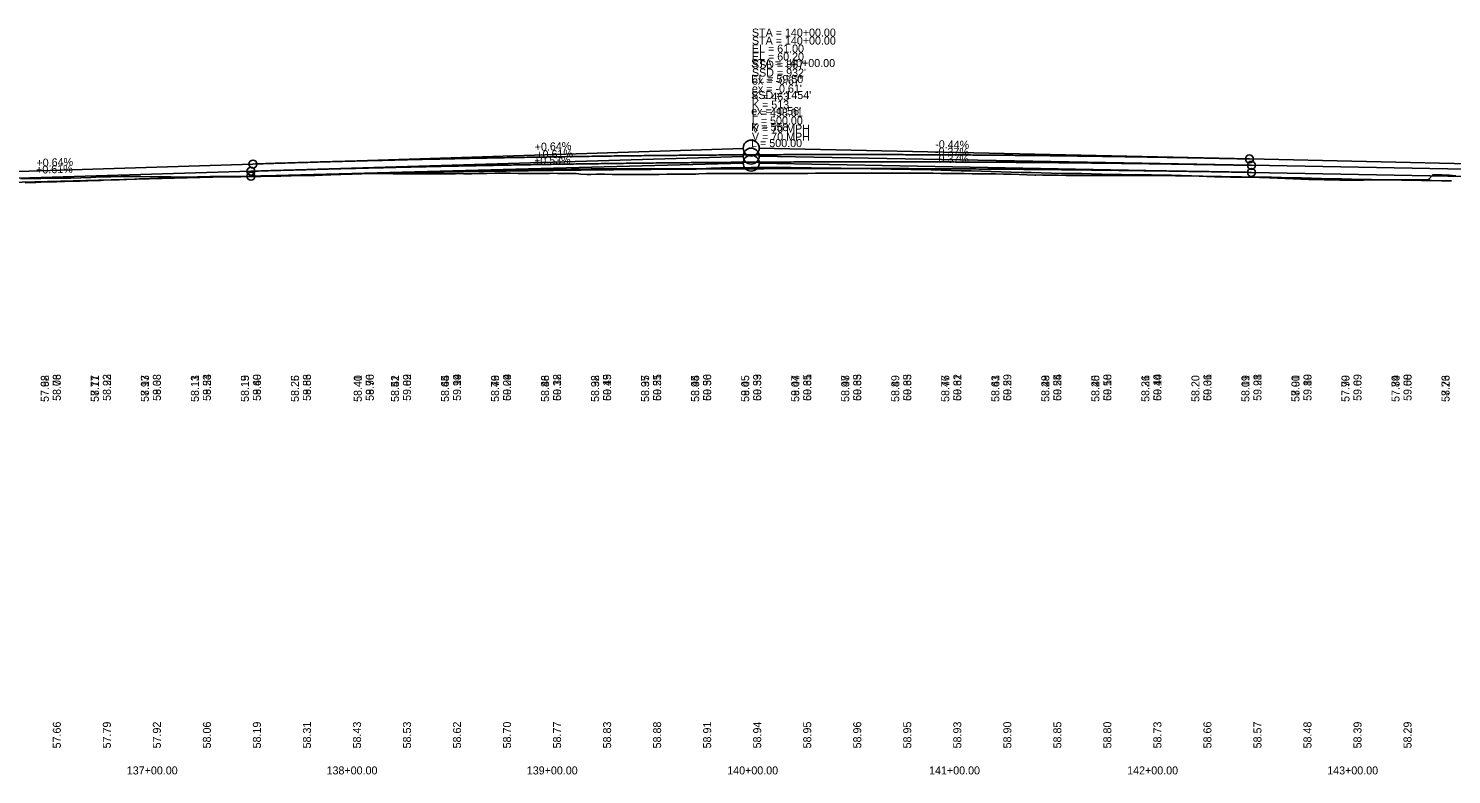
# Model space of a CAD drawing. Extents: x 3880794 to 3915434, y 287517 to 300173.
# Drawn here: x 3894177 to 3894888, y 296520 to 296893 of the extents above; entities that cross this region are included whole.
import ezdxf

# ---------------------------------------------------------------- set-up
doc = ezdxf.new("R2010")
doc.units = 0
for name, color, linetype in [('Level 1', 7, 'Continuous'), ('Level 2', 7, 'Continuous'), ('Level 30', 7, 'Continuous'), ('Level 31', 7, 'Continuous'), ('Level 32', 7, 'Continuous')]:
    doc.layers.add(name, color=color, linetype=linetype)

msp = doc.modelspace()

# ---------------------------------------------------------------- linework, layer by layer
at = {"layer": 'Level 1'}
for p, q in [((3894288.3, 296821.19), (3894534.3, 296828.64)), ((3894788.3, 296824.15), (3894542.3, 296828.68)), ((3893888.3, 296809.08), (3894288.3, 296821.19)), ((3894288.3, 296818.69), (3894534.3, 296825.15)), ((3894788.3, 296820.61), (3894542.3, 296825.18)), ((3894788.3, 296824.15), (3895938.3, 296802.96)), ((3894788.3, 296820.61), (3895938.3, 296799.26)), ((3893788.3, 296805.57), (3894288.3, 296818.69))]:
    msp.add_line(p, q, dxfattribs=at)
for points in [[(3894285.02, 296818.65), (3894288.94, 296818.69), (3894292.85, 296818.73), (3894294.38, 296818.75), (3894296.76, 296818.79), (3894298.01, 296818.81), (3894300.67, 296818.82), (3894301.29, 296818.82), (3894304.58, 296818.88), (3894308.49, 296818.94), (3894312.4, 296819.01), (3894316.31, 296819.08), (3894316.9, 296819.09), (3894320.22, 296819.15), (3894321.05, 296819.17), (3894324.13, 296819.27), (3894328.04, 296819.41), (3894331.95, 296819.55), (3894335.87, 296819.68), (3894338.96, 296819.79), (3894339.78, 296819.82), (3894342.78, 296819.92), (3894343.69, 296819.95), (3894345.76, 296820.03), (3894347.6, 296820.05), (3894349.61, 296820.08), (3894351.51, 296820.05), (3894355.42, 296819.99), (3894359.33, 296819.93), (3894363.24, 296819.88), (3894366.73, 296819.83), (3894367.15, 296819.83), (3894371.12, 296819.85), (3894374.97, 296819.83), (3894375.35, 296819.83), (3894378.88, 296819.86), (3894382.79, 296819.89), (3894386.71, 296819.93), (3894390.62, 296819.97), (3894392.25, 296819.99), (3894394.53, 296819.95), (3894398.69, 296819.9), (3894402.35, 296820), (3894406.26, 296820.1), (3894410.17, 296820.21), (3894410.58, 296820.22), (3894414.08, 296820.19), (3894417.04, 296820.17), (3894417.99, 296820.17), (3894421.9, 296820.13), (3894425.81, 296820.1), (3894427.17, 296820.09), (3894429.73, 296820.1), (3894433.32, 296820.1), (3894433.64, 296820.1), (3894436.37, 296820.1), (3894437.55, 296820.15), (3894438.2, 296820.17), (3894441.46, 296820.12), (3894445.37, 296820.05), (3894447.1, 296820.02), (3894449.28, 296820), (3894450.86, 296819.99), (3894453.19, 296819.81), (3894456.13, 296819.57), (3894457.1, 296819.58), (3894458.11, 296819.58), (3894461.01, 296819.66), (3894461.43, 296819.67), (3894462.6, 296819.66), (3894464.92, 296819.66), (3894468.83, 296819.65), (3894472.74, 296819.64), (3894476.65, 296819.64), (3894480.56, 296819.63), (3894483.18, 296819.63), (3894484.48, 296819.62), (3894486.06, 296819.61), (3894488.39, 296819.61), (3894489.07, 296819.61), (3894492.3, 296819.64), (3894496.21, 296819.67), (3894500.12, 296819.71), (3894504.03, 296819.75), (3894507.94, 296819.78), (3894510.72, 296819.81), (3894512.14, 296819.98), (3894515.76, 296820.02), (3894519.7, 296819.99), (3894523.58, 296820), (3894527.5, 296820.01), (3894531.41, 296820.01), (3894535.32, 296820.02), (3894539.23, 296820.03), (3894540.78, 296820.03), (3894541.43, 296820.03), (3894543.14, 296820.04), (3894545.19, 296820.05), (3894547.05, 296820.05), (3894550.96, 296820.06), (3894554.87, 296820.07)], [(3894554.87, 296820.07), (3894558.78, 296820.08), (3894562.69, 296820.08), (3894565.76, 296820.09), (3894566.6, 296820.1), (3894570.51, 296820.18), (3894571.13, 296820.19), (3894574.43, 296820.2), (3894575.01, 296820.2), (3894578.34, 296820.19), (3894582.25, 296820.19), (3894586.16, 296820.18), (3894590.07, 296820.17), (3894593.98, 296820.16), (3894595.12, 296820.16), (3894598.13, 296820.18), (3894600.03, 296820.18), (3894601.8, 296820.17), (3894602.96, 296820.16), (3894605.71, 296820.17), (3894609.62, 296820.2), (3894613.53, 296820.22), (3894617.44, 296820.23), (3894621.35, 296820.25), (3894623.7, 296820.26), (3894625.27, 296820.23), (3894626.43, 296820.21), (3894627.72, 296820.21), (3894629.18, 296820.19), (3894633.09, 296820.14), (3894637, 296820.09), (3894640.91, 296820.04), (3894644.82, 296819.99), (3894648.73, 296819.94), (3894651.02, 296819.91), (3894652.64, 296819.89), (3894654.9, 296819.86), (3894656.55, 296819.87), (3894657.31, 296819.87), (3894659.8, 296819.91), (3894660.46, 296819.89), (3894664.37, 296819.77), (3894668.29, 296819.66), (3894672.2, 296819.54), (3894676.11, 296819.42), (3894680.02, 296819.3), (3894680.52, 296819.29), (3894682.73, 296819.33), (3894683.93, 296819.29), (3894687.84, 296819.18), (3894689.88, 296819.18), (3894691.75, 296819.17), (3894695.66, 296819.15), (3894699.57, 296819.12), (3894703.48, 296819.09), (3894707.39, 296819.06), (3894710.44, 296819.03), (3894711.3, 296819.02), (3894712.68, 296819.01), (3894713.71, 296819), (3894715.21, 296819), (3894716.12, 296819.01), (3894719.12, 296819.02), (3894723.04, 296819.04), (3894726.95, 296819.06), (3894730.86, 296819.07), (3894734.77, 296819.09), (3894736.19, 296819.09), (3894738.68, 296819.08), (3894739.08, 296819.08), (3894742.59, 296819.08), (3894745.5, 296819.05), (3894746.5, 296819.03), (3894750.41, 296818.97), (3894754.32, 296818.91), (3894758.23, 296818.85), (3894762.14, 296818.78), (3894764, 296818.75), (3894766.06, 296818.62), (3894767.16, 296818.54), (3894769.97, 296818.42), (3894770.47, 296818.39), (3894773.88, 296818.36), (3894777.79, 296818.31), (3894781.7, 296818.27), (3894785.61, 296818.23), (3894788.74, 296818.19), (3894789.52, 296818.16), (3894792.29, 296818.08), (3894793.43, 296818.06), (3894794.57, 296818.05), (3894797.34, 296817.91), (3894801.25, 296817.72), (3894801.84, 296817.69), (3894805.16, 296817.57), (3894809.07, 296817.42), (3894812.98, 296817.26), (3894816.9, 296817.11), (3894817.6, 296817.08), (3894820.81, 296817.03), (3894824.72, 296816.96)], [(3894824.72, 296816.96), (3894826.53, 296816.93), (3894828.71, 296816.85), (3894832.54, 296816.8), (3894836.45, 296816.74), (3894840.36, 296816.69), (3894840.71, 296816.68), (3894844.27, 296816.76), (3894848.18, 296816.86), (3894852.09, 296816.94), (3894856, 296816.93), (3894857.84, 296816.93), (3894859.92, 296816.94), (3894863.83, 296816.95), (3894867.74, 296816.97), (3894871.65, 296816.98), (3894874.37, 296816.98), (3894875.56, 296816.97), (3894876.78, 296816.95), (3894877.16, 296817.38), (3894878.93, 296819.42), (3894879.69, 296819.41), (3894883.38, 296819.32), (3894886.53, 296819.24), (3894887.29, 296819.17), (3894890.4, 296818.87)], [(3894175.52, 296815.48), (3894179.43, 296815.61), (3894180.79, 296815.65), (3894183.34, 296815.72), (3894187.25, 296815.83), (3894191.17, 296815.95), (3894193.91, 296816.03), (3894195.08, 296816.06), (3894198.99, 296816.16), (3894202.93, 296816.27), (3894206.81, 296816.39), (3894210.72, 296816.52), (3894213.35, 296816.6), (3894214.63, 296816.66), (3894218.54, 296816.82), (3894221.46, 296816.92), (3894221.85, 296816.94), (3894222.45, 296816.96), (3894224.98, 296817.08), (3894226.36, 296817.13), (3894230.27, 296817.28), (3894232.48, 296817.37), (3894234.18, 296817.44), (3894238.09, 296817.61), (3894242, 296817.78), (3894245.59, 296817.94), (3894245.92, 296817.95), (3894249.83, 296818.09), (3894252.07, 296818.17), (3894253.74, 296818.2), (3894257.65, 296818.28), (3894261.56, 296818.37), (3894265.47, 296818.45), (3894267.87, 296818.5), (3894269.38, 296818.51), (3894272.84, 296818.53), (3894273.29, 296818.54), (3894277.29, 296818.58), (3894281.11, 296818.61), (3894285.02, 296818.65)]]:
    msp.add_lwpolyline(points, dxfattribs=at)
for centre in [(3894538.3, 296828.76), (3894538.3, 296825.26)]:
    msp.add_circle(centre, 4, dxfattribs=at)
for points in [[(3894288.3, 296821.19), (3894298.3, 296821.49), (3894308.3, 296821.77), (3894318.3, 296822.05), (3894328.3, 296822.32), (3894338.3, 296822.58), (3894348.3, 296822.83), (3894358.3, 296823.07), (3894368.3, 296823.3), (3894378.3, 296823.52), (3894388.3, 296823.73), (3894398.3, 296823.93), (3894408.3, 296824.12), (3894418.3, 296824.3), (3894428.3, 296824.47), (3894438.3, 296824.63), (3894448.3, 296824.79), (3894458.3, 296824.93), (3894468.3, 296825.06), (3894478.3, 296825.18), (3894488.3, 296825.29), (3894498.3, 296825.4), (3894508.3, 296825.49), (3894518.3, 296825.57), (3894528.3, 296825.65), (3894538.3, 296825.71), (3894548.3, 296825.77), (3894558.3, 296825.81), (3894568.3, 296825.85), (3894578.3, 296825.87), (3894588.3, 296825.89), (3894598.3, 296825.89), (3894608.3, 296825.89), (3894618.3, 296825.88), (3894628.3, 296825.85), (3894638.3, 296825.82), (3894648.3, 296825.78), (3894658.3, 296825.72), (3894668.3, 296825.66), (3894678.3, 296825.59), (3894688.3, 296825.51), (3894698.3, 296825.41), (3894708.3, 296825.31), (3894718.3, 296825.2), (3894728.3, 296825.08), (3894738.3, 296824.95), (3894748.3, 296824.81), (3894758.3, 296824.66), (3894768.3, 296824.5), (3894778.3, 296824.33), (3894788.3, 296824.15)], [(3894288.3, 296818.69), (3894298.3, 296818.95), (3894308.3, 296819.2), (3894318.3, 296819.44), (3894328.3, 296819.67), (3894338.3, 296819.89), (3894348.3, 296820.11), (3894358.3, 296820.31), (3894368.3, 296820.51), (3894378.3, 296820.69), (3894388.3, 296820.87), (3894398.3, 296821.04), (3894408.3, 296821.2), (3894418.3, 296821.35), (3894428.3, 296821.49), (3894438.3, 296821.62), (3894448.3, 296821.75), (3894458.3, 296821.86), (3894468.3, 296821.97), (3894478.3, 296822.06), (3894488.3, 296822.15), (3894498.3, 296822.23), (3894508.3, 296822.3), (3894518.3, 296822.36), (3894528.3, 296822.41), (3894538.3, 296822.46), (3894548.3, 296822.49), (3894558.3, 296822.51), (3894568.3, 296822.53), (3894578.3, 296822.54), (3894588.3, 296822.54), (3894598.3, 296822.52), (3894608.3, 296822.5), (3894618.3, 296822.48), (3894628.3, 296822.44), (3894638.3, 296822.39), (3894648.3, 296822.34), (3894658.3, 296822.27), (3894668.3, 296822.2), (3894678.3, 296822.11), (3894688.3, 296822.02), (3894698.3, 296821.92), (3894708.3, 296821.81), (3894718.3, 296821.69), (3894728.3, 296821.57), (3894738.3, 296821.43), (3894748.3, 296821.29), (3894758.3, 296821.13), (3894768.3, 296820.97), (3894778.3, 296820.8), (3894788.3, 296820.61)]]:
    msp.add_spline(points, degree=3, dxfattribs=at)
at = {"layer": 'Level 2'}
for p, q in [((3894289.29, 296824.8), (3894534.3, 296832.63)), ((3894787.3, 296827.33), (3894542.3, 296832.67)), ((3894787.3, 296827.33), (3895938.3, 296802.26)), ((3893888.3, 296811.99), (3894289.29, 296824.8))]:
    msp.add_line(p, q, dxfattribs=at)
for points in [[(3894173.3, 296817.4), (3894178.3, 296817.55), (3894183.3, 296817.62), (3894188.3, 296817.67), (3894193.3, 296817.71), (3894198.3, 296817.81), (3894203.3, 296817.93), (3894208.3, 296818.09), (3894213.3, 296818.32), (3894218.3, 296818.42), (3894223.3, 296818.5), (3894228.3, 296818.57), (3894233.3, 296818.62), (3894238.3, 296818.39), (3894243.3, 296818.49), (3894248.3, 296818.38), (3894253.3, 296818.29), (3894258.3, 296818.28), (3894263.3, 296818.32), (3894268.3, 296818.33), (3894273.3, 296818.34), (3894278.3, 296818.35), (3894283.3, 296818.4), (3894288.3, 296818.52), (3894293.3, 296818.62), (3894298.3, 296818.71), (3894303.3, 296818.8), (3894308.3, 296818.94), (3894313.3, 296819.05), (3894318.3, 296819.19), (3894323.3, 296819.33), (3894328.3, 296819.46), (3894333.3, 296819.59), (3894338.3, 296819.78), (3894343.3, 296819.89), (3894348.3, 296819.99), (3894353.3, 296820.09), (3894358.3, 296820.19), (3894363.3, 296820.33), (3894368.3, 296820.47), (3894373.3, 296820.6), (3894378.3, 296820.73), (3894383.3, 296820.86), (3894388.3, 296820.99), (3894393.3, 296821.05), (3894398.3, 296821.17), (3894403.3, 296821.31), (3894408.3, 296821.44), (3894413.3, 296821.57), (3894418.3, 296821.72), (3894423.3, 296821.83), (3894428.3, 296821.86), (3894433.3, 296821.95), (3894438.3, 296822.04), (3894443.3, 296822.13), (3894448.3, 296822.22), (3894453.3, 296822.27), (3894458.3, 296822.32), (3894463.3, 296822.36), (3894468.3, 296822.4), (3894473.3, 296822.43), (3894478.3, 296822.46), (3894483.3, 296822.48), (3894488.3, 296822.49), (3894493.3, 296822.47), (3894498.3, 296822.44), (3894503.3, 296822.41), (3894508.3, 296822.38), (3894513.3, 296822.48), (3894518.3, 296822.65), (3894523.3, 296822.82), (3894528.3, 296822.99), (3894533.3, 296822.97), (3894538.3, 296823)], [(3894538.3, 296823), (3894543.3, 296823.03), (3894548.3, 296823.06), (3894553.3, 296823.12), (3894558.3, 296823.03), (3894563.3, 296822.93), (3894568.3, 296822.83), (3894573.3, 296822.75), (3894578.3, 296822.7), (3894583.3, 296822.65), (3894588.3, 296822.6), (3894593.3, 296822.54), (3894598.3, 296822.48), (3894603.3, 296822.38), (3894608.3, 296822.29), (3894613.3, 296822.19), (3894618.3, 296822.1), (3894623.3, 296822), (3894628.3, 296821.87), (3894633.3, 296821.73), (3894638.3, 296821.6), (3894643.3, 296821.45), (3894648.3, 296821.32), (3894653.3, 296821.18), (3894658.3, 296821.05), (3894663.3, 296820.91), (3894668.3, 296820.77), (3894673.3, 296820.62), (3894678.3, 296820.51), (3894683.3, 296820.36), (3894688.3, 296820.2), (3894693.3, 296820.03), (3894698.3, 296820.07), (3894703.3, 296820.05), (3894708.3, 296819.97), (3894713.3, 296819.78), (3894718.3, 296819.62), (3894723.3, 296819.49), (3894728.3, 296819.43), (3894733.3, 296819.38), (3894738.3, 296819.32), (3894743.3, 296819.27), (3894748.3, 296819.2), (3894753.3, 296819.06), (3894758.3, 296818.92), (3894763.3, 296818.78), (3894768.3, 296818.63), (3894773.3, 296818.52), (3894778.3, 296818.46), (3894783.3, 296818.39), (3894788.3, 296818.31), (3894793.3, 296818.24), (3894798.3, 296818.17), (3894803.3, 296818.05), (3894808.3, 296817.94), (3894813.3, 296817.83), (3894818.3, 296817.71), (3894823.3, 296817.6), (3894828.3, 296817.47), (3894833.3, 296817.36), (3894838.3, 296817.25), (3894843.3, 296817.14), (3894848.3, 296817.05), (3894853.3, 296816.95), (3894858.3, 296816.86), (3894863.3, 296816.72), (3894868.3, 296816.66), (3894873.3, 296816.59), (3894878.3, 296816.52), (3894883.3, 296816.45), (3894888.3, 296816.38)]]:
    msp.add_lwpolyline(points, dxfattribs=at)
for centre, radius in [((3894538.3, 296832.76), 4), ((3894289.29, 296824.8), 2), ((3894787.3, 296827.33), 2)]:
    msp.add_circle(centre, radius, dxfattribs=at)
msp.add_spline([(3894289.29, 296824.8), (3894299.25, 296825.12), (3894309.21, 296825.42), (3894319.17, 296825.71), (3894329.13, 296825.99), (3894339.09, 296826.26), (3894349.05, 296826.52), (3894359.01, 296826.77), (3894368.97, 296827.01), (3894378.93, 296827.23), (3894388.89, 296827.45), (3894398.85, 296827.65), (3894408.81, 296827.85), (3894418.77, 296828.03), (3894428.73, 296828.21), (3894438.7, 296828.37), (3894448.66, 296828.52), (3894458.62, 296828.66), (3894468.58, 296828.8), (3894478.54, 296828.92), (3894488.5, 296829.03), (3894498.46, 296829.12), (3894508.42, 296829.21), (3894518.38, 296829.29), (3894528.34, 296829.36), (3894538.3, 296829.41), (3894548.26, 296829.46), (3894558.22, 296829.49), (3894568.18, 296829.52), (3894578.14, 296829.53), (3894588.1, 296829.53), (3894598.06, 296829.52), (3894608.02, 296829.5), (3894617.98, 296829.47), (3894627.94, 296829.43), (3894637.9, 296829.38), (3894647.86, 296829.32), (3894657.82, 296829.25), (3894667.78, 296829.17), (3894677.74, 296829.07), (3894687.7, 296828.97), (3894697.66, 296828.85), (3894707.62, 296828.73), (3894717.58, 296828.59), (3894727.54, 296828.44), (3894737.5, 296828.28), (3894747.46, 296828.11), (3894757.42, 296827.94), (3894767.38, 296827.74), (3894777.34, 296827.54), (3894787.3, 296827.33)], degree=3, dxfattribs=at)
at = {"layer": 'Level 31'}
for centre in [(3894788.3, 296824.15), (3894288.3, 296821.19), (3894288.3, 296818.69), (3894788.3, 296820.61)]:
    msp.add_circle(centre, 2, dxfattribs=at)

# ---------------------------------------------------------------- texts
at = {"layer": 'Level 2'}
for s, p in [('STA = 140+00.00', (3894538.67, 296888.49)), ('EL = 61.00', (3894538.67, 296880.49)), ("SSD = 867'", (3894538.67, 296872.49)), ("ex = -0.67'", (3894538.67, 296864.49)), ('K = 463', (3894538.67, 296856.49)), ('L = 498.01', (3894538.67, 296848.49)), ('V = 70 MPH', (3894538.67, 296840.49)), ('137+00.00', (3894226.27, 296519.76)), ('138+00.00', (3894326.11, 296519.76)), ('139+00.00', (3894426.17, 296519.76)), ('140+00.00', (3894526.33, 296519.76)), ('141+00.00', (3894627.21, 296519.76)), ('142+00.00', (3894726.2, 296519.76)), ('143+00.00', (3894826.17, 296519.76))]:
    msp.add_text(s, height=4, dxfattribs=at).set_placement(p)
for s, rotation, p in [('+0.64%', 1.82966, (3894430.19, 296831.31)), ('-0.44%', 358.75197, (3894630.23, 296832.76)), ('+0.64%', 1.82966, (3894181.19, 296823.35)), ('58.76', 90, (3894193.3, 296706.43)), ('58.92', 90, (3894218.3, 296706.43)), ('59.08', 90, (3894243.3, 296706.43)), ('59.24', 90, (3894268.3, 296706.43)), ('59.40', 90, (3894293.3, 296706.43)), ('59.56', 90, (3894318.3, 296706.43)), ('59.70', 90, (3894349.71, 296706.43)), ('59.82', 90, (3894368.3, 296706.43)), ('59.94', 90, (3894393.3, 296706.43)), ('60.04', 90, (3894418.3, 296706.43)), ('60.12', 90, (3894443.3, 296706.43)), ('60.19', 90, (3894468.3, 296706.43)), ('60.25', 90, (3894493.3, 296706.43)), ('60.30', 90, (3894518.3, 296706.43)), ('60.33', 90, (3894543.3, 296706.43)), ('60.35', 90, (3894568.3, 296706.43)), ('60.35', 90, (3894593.3, 296706.43)), ('60.35', 90, (3894618.3, 296706.43)), ('60.32', 90, (3894643.3, 296706.43)), ('60.29', 90, (3894668.3, 296706.43)), ('60.24', 90, (3894693.3, 296706.43)), ('60.18', 90, (3894718.3, 296706.43)), ('60.10', 90, (3894743.3, 296706.43)), ('60.01', 90, (3894768.3, 296706.43)), ('59.91', 90, (3894793.3, 296706.43)), ('59.80', 90, (3894818.3, 296706.43)), ('59.69', 90, (3894843.3, 296706.43)), ('59.58', 90, (3894868.3, 296706.43))]:
    msp.add_text(s, height=4, rotation=rotation, dxfattribs=at).set_placement(p)
at = {"layer": 'Level 30'}
for s, p in [('57.62', (3894187.3, 296705.91)), ('57.77', (3894212.3, 296705.91)), ('57.97', (3894237.3, 296705.91)), ('58.13', (3894262.3, 296705.91)), ('58.19', (3894287.3, 296705.91)), ('58.25', (3894312.3, 296705.91)), ('58.40', (3894343.71, 296705.91)), ('58.42', (3894362.3, 296705.91)), ('58.44', (3894387.3, 296705.91)), ('58.49', (3894412.3, 296705.91)), ('58.48', (3894437.3, 296705.91)), ('58.38', (3894462.3, 296705.91)), ('58.37', (3894487.3, 296705.91)), ('58.45', (3894512.3, 296705.91)), ('58.45', (3894537.3, 296705.91)), ('58.47', (3894562.3, 296705.91)), ('58.48', (3894587.3, 296705.91)), ('58.49', (3894612.3, 296705.91)), ('58.46', (3894637.3, 296705.91)), ('58.41', (3894662.3, 296705.91)), ('58.28', (3894687.3, 296705.91)), ('58.25', (3894712.3, 296705.91)), ('58.26', (3894737.3, 296705.91)), ('58.20', (3894762.3, 296705.91)), ('58.09', (3894787.3, 296705.91)), ('57.90', (3894812.3, 296705.91)), ('57.79', (3894837.3, 296705.91)), ('57.84', (3894862.3, 296705.91)), ('58.26', (3894887.3, 296705.91))]:
    msp.add_text(s, height=4, rotation=90, dxfattribs=at).set_placement(p)
for s, p in [('137+00.00', (3894226.27, 296519.76)), ('137+00.00', (3894226.27, 296519.76)), ('137+00.00', (3894226.27, 296519.76)), ('138+00.00', (3894326.11, 296519.76)), ('138+00.00', (3894326.11, 296519.76)), ('138+00.00', (3894326.11, 296519.76)), ('139+00.00', (3894426.17, 296519.76)), ('139+00.00', (3894426.17, 296519.76)), ('139+00.00', (3894426.17, 296519.76)), ('140+00.00', (3894526.33, 296519.76)), ('140+00.00', (3894526.33, 296519.76)), ('140+00.00', (3894526.33, 296519.76)), ('141+00.00', (3894627.21, 296519.76)), ('141+00.00', (3894627.21, 296519.76)), ('141+00.00', (3894627.21, 296519.76)), ('142+00.00', (3894726.2, 296519.76)), ('142+00.00', (3894726.2, 296519.76)), ('142+00.00', (3894726.2, 296519.76)), ('143+00.00', (3894826.17, 296519.76)), ('143+00.00', (3894826.17, 296519.76)), ('143+00.00', (3894826.17, 296519.76))]:
    msp.add_text(s, height=4, dxfattribs=at).set_placement(p)
at = {"layer": 'Level 31'}
for s, p in [('STA = 140+00.00', (3894538.67, 296884.49)), ('STA = 140+00.00', (3894538.3, 296873.26)), ('EL = 60.20', (3894538.67, 296876.49)), ('EL = 59.50', (3894538.3, 296865.26)), ("SSD = 932'", (3894538.67, 296868.49)), ("ex = -0.61'", (3894538.67, 296860.49)), ("SSD = 1454'", (3894538.3, 296857.26)), ('K = 513', (3894538.67, 296852.49)), ("ex = -0.56'", (3894538.3, 296849.26)), ('L = 500.00', (3894538.67, 296844.49)), ('V = 70 MPH', (3894538.67, 296836.49)), ('K = 558', (3894538.3, 296841.26)), ('L = 500.00', (3894538.3, 296833.26))]:
    msp.add_text(s, height=4, dxfattribs=at).set_placement(p)
for s, rotation, p in [('-0.37%', 358.94424, (3894630.1, 296829.07)), ('+0.53%', 1.50367, (3894429.84, 296824.41)), ('+0.61%', 1.73426, (3894431.01, 296827.51)), ('-0.37%', 358.93606, (3894630.1, 296825.55)), ('+0.61%', 1.73426, (3894181.01, 296819.94)), ('58.08', 90, (3894193.3, 296706.43)), ('58.23', 90, (3894218.3, 296706.43)), ('58.38', 90, (3894243.3, 296706.43)), ('58.53', 90, (3894268.3, 296706.43)), ('58.69', 90, (3894293.3, 296706.43)), ('58.83', 90, (3894318.3, 296706.43)), ('58.96', 90, (3894349.71, 296706.43)), ('59.09', 90, (3894368.3, 296706.43)), ('59.19', 90, (3894393.3, 296706.43)), ('59.29', 90, (3894418.3, 296706.43)), ('59.38', 90, (3894443.3, 296706.43)), ('59.45', 90, (3894468.3, 296706.43)), ('59.51', 90, (3894493.3, 296706.43)), ('59.56', 90, (3894518.3, 296706.43)), ('59.59', 90, (3894543.3, 296706.43)), ('59.61', 90, (3894568.3, 296706.43)), ('59.63', 90, (3894593.3, 296706.43)), ('59.63', 90, (3894618.3, 296706.43)), ('59.61', 90, (3894643.3, 296706.43)), ('59.59', 90, (3894668.3, 296706.43)), ('59.55', 90, (3894693.3, 296706.43)), ('59.50', 90, (3894718.3, 296706.43)), ('59.44', 90, (3894743.3, 296706.43)), ('59.36', 90, (3894768.3, 296706.43)), ('59.28', 90, (3894793.3, 296706.43)), ('59.19', 90, (3894818.3, 296706.43)), ('59.09', 90, (3894843.3, 296706.43)), ('59.00', 90, (3894868.3, 296706.43)), ('57.66', 90, (3894193.3, 296532.76)), ('57.79', 90, (3894218.3, 296532.76)), ('57.92', 90, (3894243.3, 296532.76)), ('58.06', 90, (3894268.3, 296532.76)), ('58.19', 90, (3894293.3, 296532.76)), ('58.31', 90, (3894318.3, 296532.76)), ('58.43', 90, (3894343.3, 296532.76)), ('58.53', 90, (3894368.3, 296532.76)), ('58.62', 90, (3894393.3, 296532.76)), ('58.70', 90, (3894418.3, 296532.76)), ('58.77', 90, (3894443.3, 296532.76)), ('58.83', 90, (3894468.3, 296532.76)), ('58.88', 90, (3894493.3, 296532.76)), ('58.91', 90, (3894518.3, 296532.76)), ('58.94', 90, (3894543.3, 296532.76)), ('58.95', 90, (3894568.3, 296532.76)), ('58.96', 90, (3894593.3, 296532.76)), ('58.95', 90, (3894618.3, 296532.76)), ('58.93', 90, (3894643.3, 296532.76)), ('58.90', 90, (3894668.3, 296532.76)), ('58.85', 90, (3894693.3, 296532.76)), ('58.80', 90, (3894718.3, 296532.76)), ('58.73', 90, (3894743.3, 296532.76)), ('58.66', 90, (3894768.3, 296532.76)), ('58.57', 90, (3894793.3, 296532.76)), ('58.48', 90, (3894818.3, 296532.76)), ('58.39', 90, (3894843.3, 296532.76)), ('58.29', 90, (3894868.3, 296532.76))]:
    msp.add_text(s, height=4, rotation=rotation, dxfattribs=at).set_placement(p)
at = {"layer": 'Level 32'}
for s, p in [('57.98', (3894187.3, 296705.91)), ('58.11', (3894212.3, 296705.91)), ('58.13', (3894237.3, 296705.91)), ('58.11', (3894262.3, 296705.91)), ('58.15', (3894287.3, 296705.91)), ('58.26', (3894312.3, 296705.91)), ('58.41', (3894343.71, 296705.91)), ('58.51', (3894362.3, 296705.91)), ('58.65', (3894387.3, 296705.91)), ('58.76', (3894412.3, 296705.91)), ('58.86', (3894437.3, 296705.91)), ('58.92', (3894462.3, 296705.91)), ('58.95', (3894487.3, 296705.91)), ('58.94', (3894512.3, 296705.91)), ('59.05', (3894537.3, 296705.91)), ('59.04', (3894562.3, 296705.91)), ('58.97', (3894587.3, 296705.91)), ('58.89', (3894612.3, 296705.91)), ('58.77', (3894637.3, 296705.91)), ('58.63', (3894662.3, 296705.91)), ('58.49', (3894687.3, 296705.91)), ('58.40', (3894712.3, 296705.91)), ('58.31', (3894737.3, 296705.91)), ('58.20', (3894762.3, 296705.91)), ('58.11', (3894787.3, 296705.91)), ('58.01', (3894812.3, 296705.91)), ('57.90', (3894837.3, 296705.91)), ('57.79', (3894862.3, 296705.91)), ('57.73', (3894887.3, 296705.91))]:
    msp.add_text(s, height=4, rotation=90, dxfattribs=at).set_placement(p)

doc.saveas('drawing.dxf')
